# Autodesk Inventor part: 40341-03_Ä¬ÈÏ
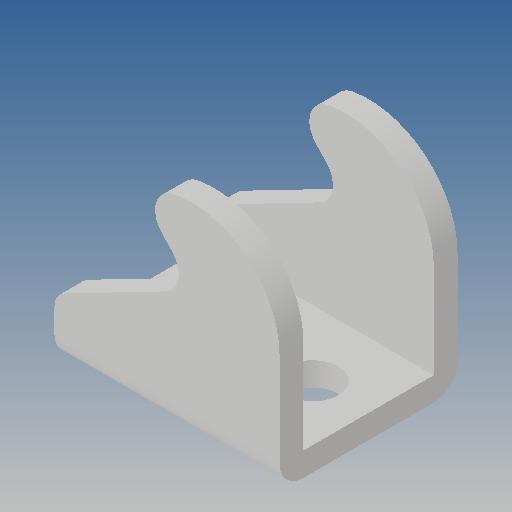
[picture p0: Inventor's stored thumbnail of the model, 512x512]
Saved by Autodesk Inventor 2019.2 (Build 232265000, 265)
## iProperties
Created: 2010-06
Part Number: 40341-03_Ä¬ÈÏ
Material: Ogólny
Document SubType Name: Modeling
Designer: CADENGINEERING4
Density: 1 g/cm^3
Appearance: Domyślna
Author: CADENGINEERING4
Revision Number: ÈÎºÎ
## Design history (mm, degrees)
feature "NONE"
node "Bryła1"
